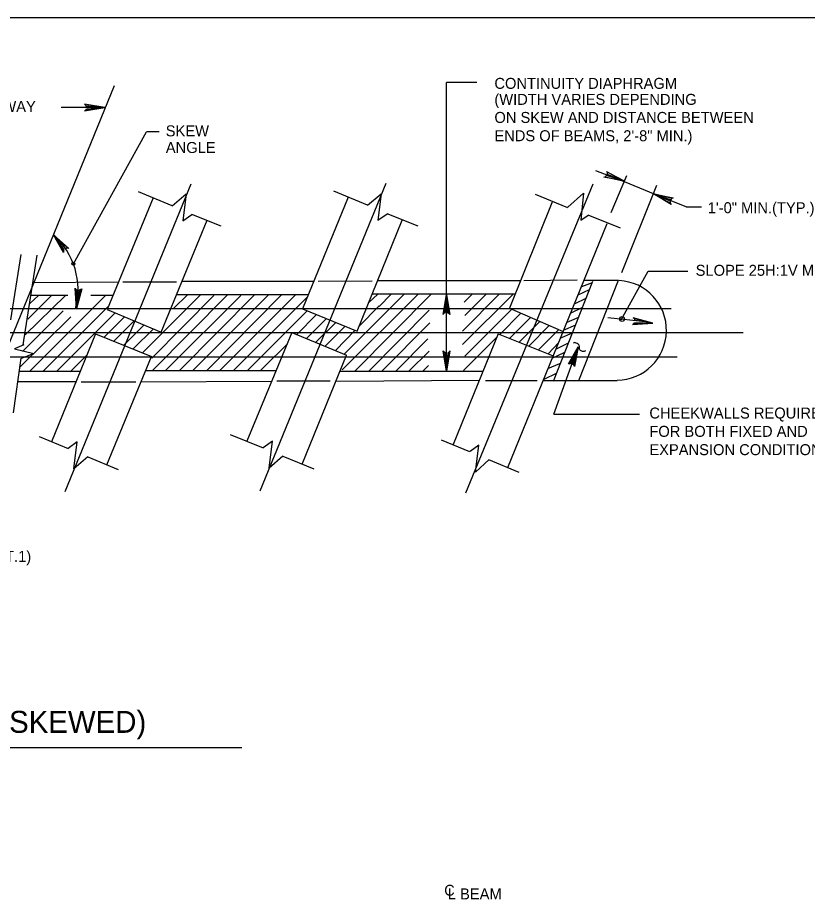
# Model space of a CAD drawing. Extents: x 639980 to 641204, y 298038 to 300414.
# Drawn here: x 640257.8 to 640473.5, y 298970 to 299210.8 of the extents above; entities that cross this region are included whole.
import ezdxf

# ---------------------------------------------------------------- set-up
doc = ezdxf.new("R2010")
doc.units = 0
doc.layers.add('2', color=7, linetype='Continuous')
doc.layers.add('3', color=7, linetype='Continuous')

msp = doc.modelspace()

# ---------------------------------------------------------------- linework, layer by layer
at = {"layer": '2'}
for p, q in [((640020.31, 299210.78), (640806.31, 299210.78)), ((640237.04, 299076.6), (640284.31, 299192.29)), ((640374.92, 299135.1), (640374.92, 299193.06)), ((640383.2, 299193.06), (640374.92, 299193.06)), ((640281.64, 299186.27), (640269.76, 299186.27)), ((640273.04, 299143.56), (640293.02, 299179.56)), ((640296.44, 299179.56), (640293.02, 299179.56)), ((640423.49, 299165.91), (640415.75, 299168.97)), ((640419.93, 299157.56), (640424.21, 299167.71)), ((640305.08, 299165.34), (640270.7, 299081.28)), ((640358.36, 299165.52), (640323.98, 299081.46)), ((640414.88, 299165.34), (640380.14, 299080.92)), ((640422.8, 299141.22), (640432.35, 299164.99)), ((640431.95, 299162.49), (640423.49, 299165.91)), ((640300.04, 299159.4), (640290.86, 299163.18)), ((640353.32, 299159.58), (640344.14, 299163.36)), ((640408.04, 299158.86), (640399.22, 299162.46)), ((640440.41, 299159.07), (640431.41, 299162.67)), ((640294.82, 299161.56), (640282.29, 299131.05)), ((640348.1, 299161.74), (640335.57, 299131.23)), ((640403.9, 299160.66), (640392.09, 299131.41)), ((640367.18, 299153.82), (640358.72, 299157.24)), ((640440.41, 299159.07), (640444.55, 299159.07)), ((640297.06, 299124.93), (640309.58, 299155.44)), ((640313.36, 299153.82), (640305.44, 299157.06)), ((640350.55, 299125.17), (640362.86, 299155.44)), ((640422.44, 299153.28), (640413.62, 299156.88)), ((640391.66, 299087.94), (640418.84, 299154.54)), ((640255.94, 299128.26), (640258.82, 299146.08)), ((640259.36, 299121.42), (640263.14, 299145.9)), ((640422.62, 299128.26), (640430, 299141.58)), ((640430, 299141.58), (640440.8, 299141.58)), ((640285.28, 299138.52), (640262.06, 299138.34)), ((640301.19, 299138.52), (640286.53, 299138.52)), ((640338.64, 299138.7), (640302.74, 299138.7)), ((640354.65, 299138.84), (640339.87, 299138.73)), ((640395.11, 299138.88), (640356.13, 299138.88)), ((640410.59, 299139.05), (640396.03, 299138.93)), ((640404.12, 299111.47), (640414.92, 299138.83)), ((640411.1, 299111.7), (640421.9, 299139.06)), ((640414.74, 299138.38), (640411.82, 299137.26)), ((640412.54, 299139.06), (640421.9, 299139.06)), ((640410.92, 299135.1), (640414.01, 299136.53)), ((640271.53, 299134.92), (640261.52, 299134.92)), ((640283.84, 299134.92), (640277.85, 299134.92)), ((640337.12, 299135.1), (640301.3, 299135.1)), ((640393.64, 299135.28), (640354.58, 299135.28)), ((640374.92, 299114.22), (640374.92, 299135.1)), ((640410.02, 299132.76), (640413.08, 299134.17)), ((640103.87, 299131.32), (640436.3, 299131.32)), ((640282.29, 299131.05), (640297.06, 299124.93)), ((640335.57, 299131.23), (640350.55, 299125.17)), ((640392.09, 299131.41), (640406.83, 299125.1)), ((640408.76, 299130.06), (640412.12, 299131.74)), ((640410.97, 299128.88), (640407.79, 299127.52)), ((640429.28, 299127.72), (640419.02, 299128.8)), ((640406.88, 299125.4), (640410.25, 299126.85)), ((640455.92, 299124.66), (640202.59, 299124.66)), ((640279.1, 299124.45), (640267.1, 299094.96)), ((640279.1, 299124.45), (640294.39, 299118.27)), ((640332.67, 299124.84), (640320.38, 299095.14)), ((640332.67, 299124.84), (640347.67, 299118.63)), ((640389.08, 299124.42), (640376.72, 299094.24)), ((640389.08, 299124.42), (640404.01, 299118.45)), ((640405.98, 299123.23), (640409.32, 299124.66)), ((640404.98, 299120.34), (640408.27, 299121.98)), ((640403.8, 299117.79), (640407.08, 299119.3)), ((640404.26, 299102.52), (640410.92, 299120.88)), ((640148.46, 299118.18), (640437.92, 299118.18)), ((640256.66, 299102.88), (640258.82, 299117.82)), ((640282.22, 299088.66), (640294.39, 299118.27)), ((640335.5, 299088.84), (640347.67, 299118.63)), ((640402.62, 299114.95), (640405.91, 299116.36)), ((640258.28, 299114.22), (640275.02, 299114.22)), ((640292.66, 299114.4), (640328.3, 299114.4)), ((640345.94, 299114.22), (640385, 299114.22)), ((640291.58, 299111.34), (640327.17, 299111.54)), ((640343.15, 299111.52), (640328.6, 299111.52)), ((640344.76, 299111.5), (640383.89, 299111.74)), ((640385.55, 299111.7), (640399.65, 299111.7)), ((640401.36, 299111.7), (640421.54, 299111.7)), ((640401.56, 299112.06), (640404.98, 299113.66)), ((640273.76, 299111.34), (640257.92, 299111.34)), ((640275.14, 299111.34), (640290.14, 299111.34)), ((640404.26, 299102.52), (640427.66, 299102.52)), ((640263.68, 299096.4), (640271.6, 299093.16)), ((640315.88, 299096.94), (640324.88, 299093.34)), ((640373.48, 299095.5), (640381.22, 299092.26)), ((640277, 299090.82), (640285.28, 299087.4)), ((640330.28, 299091), (640338.74, 299087.58)), ((640386.44, 299090.1), (640394.72, 299086.68)), ((640202.29, 299011.49), (640319.04, 299011.49))]:
    msp.add_line(p, q, dxfattribs=at)
for points in [[(640276.42, 299185.55), (640276.6, 299185.91), (640281.64, 299186.27), (640276.42, 299185.55), (640276.06, 299185.37), (640281.64, 299186.27), (640276.6, 299186.45), (640276.42, 299186.81), (640281.64, 299186.27), (640276.06, 299187.17), (640276.42, 299186.81)], [(640276.42, 299185.55), (640276.6, 299185.91), (640281.64, 299186.27), (640276.42, 299185.55), (640276.06, 299185.37), (640281.64, 299186.27), (640276.6, 299186.45), (640276.42, 299186.81), (640281.64, 299186.27), (640276.06, 299187.17), (640276.42, 299186.81)], [(640418.81, 299168.61), (640418.81, 299168.07), (640423.49, 299166.09), (640418.81, 299168.61), (640418.63, 299168.79), (640423.49, 299166.09), (640418.63, 299167.71), (640418.27, 299167.35), (640423.49, 299166.09), (640417.91, 299167.17), (640418.27, 299167.35)], [(640300.04, 299159.4), (640303.82, 299162.64), (640302.92, 299155.26), (640305.44, 299157.06)], [(640353.32, 299159.58), (640357.1, 299162.64), (640356.2, 299155.44), (640358.72, 299157.24)], [(640408.04, 299159.04), (640412.36, 299162.82), (640411.64, 299155.44), (640413.62, 299156.88)], [(640436.09, 299160.15), (640436.09, 299160.69), (640431.41, 299162.67), (640436.09, 299160.15), (640436.27, 299159.79), (640431.41, 299162.67), (640436.27, 299161.05), (640436.45, 299161.41), (640431.41, 299162.67), (640436.81, 299161.59), (640436.45, 299161.41)], [(640270.34, 299146.98), (640270.52, 299147.34), (640267.64, 299151.48), (640270.34, 299146.98), (640270.34, 299146.62), (640267.64, 299151.48), (640270.88, 299147.7), (640271.42, 299147.88), (640267.64, 299151.48), (640271.78, 299147.7), (640271.42, 299147.88)], [(640275.02, 299136.54), (640274.66, 299136.36), (640273.94, 299131.32), (640275.02, 299136.54), (640275.38, 299136.72), (640273.94, 299131.32), (640274.12, 299136.36), (640273.76, 299136.54), (640273.94, 299131.32), (640273.58, 299136.9), (640273.76, 299136.54)], [(640259.9, 299124.12), (640270.88, 299134.92)], [(640260.62, 299128.44), (640267.1, 299134.92)], [(640261.16, 299114.22), (640281.86, 299134.92)], [(640261.16, 299132.76), (640263.5, 299134.92)], [(640294.46, 299117.82), (640311.39, 299134.93)], [(640294.64, 299114.4), (640315.02, 299134.96)], [(640298.24, 299114.4), (640318.75, 299134.9)], [(640300.5, 299131.42), (640304.18, 299135.1)], [(640302.02, 299114.4), (640322.59, 299135.15)], [(640303.22, 299130.54), (640307.65, 299134.97)], [(640305.68, 299114.46), (640326.32, 299135.1)], [(640309.55, 299114.55), (640329.92, 299135.1)], [(640312.97, 299114.37), (640333.7, 299135.1)], [(640316.78, 299114.4), (640336.94, 299134.55)], [(640346.48, 299114.58), (640367.18, 299135.28)], [(640347.02, 299118.9), (640363.4, 299135.28)], [(640349.9, 299114.22), (640370.78, 299135.28)], [(640353.72, 299132.95), (640356.2, 299135.28)], [(640356.56, 299131.86), (640359.8, 299135.28)], [(640374.2, 299130.06), (640374.56, 299130.24), (640374.92, 299135.1), (640374.2, 299130.06), (640374.02, 299129.7), (640374.92, 299135.1), (640375.1, 299130.24), (640375.46, 299130.06), (640374.92, 299135.1), (640375.82, 299129.7), (640375.46, 299130.06)], [(640379.26, 299125.13), (640389.32, 299135.28)], [(640379.34, 299121.52), (640393.1, 299135.28)], [(640379.72, 299133.04), (640381.94, 299135.28)], [(640379.91, 299129.47), (640385.72, 299135.28)], [(640259.18, 299119.62), (640270.28, 299130.72)], [(640264.76, 299114.22), (640282.58, 299131.86)], [(640291.89, 299119.21), (640303.51, 299130.83)], [(640320.56, 299114.4), (640336.87, 299130.71)], [(640351.09, 299126.48), (640356.56, 299132.04)], [(640353.68, 299114.22), (640370.22, 299130.9)], [(640379.96, 299118.36), (640392.74, 299131.14)], [(640258.46, 299115.3), (640272.38, 299129.09)], [(640273.94, 299119.62), (640284.47, 299130.15)], [(640281.43, 299123.51), (640287.02, 299129.1)], [(640334.04, 299124.28), (640339.43, 299129.67)], [(640336.71, 299123.17), (640342.12, 299128.58)], [(640389.47, 299124.26), (640395.26, 299130.06)], [(640392.17, 299123.18), (640397.9, 299128.92)], [(640426.04, 299127.18), (640426.22, 299127.54), (640431.26, 299127.36), (640426.04, 299127.18), (640425.68, 299127), (640431.26, 299127.36), (640426.4, 299128.08), (640426.22, 299128.62), (640431.26, 299127.36), (640425.86, 299128.8), (640426.22, 299128.62)], [(640284.12, 299122.42), (640289.69, 299127.99)], [(640286.81, 299121.33), (640292.36, 299126.88)], [(640339.26, 299122.12), (640344.69, 299127.54)], [(640341.8, 299121.06), (640347.25, 299126.51)], [(640357.28, 299114.22), (640370.34, 299127.39)], [(640394.74, 299122.16), (640400.42, 299127.84)], [(640397.42, 299121.06), (640402.97, 299126.75)], [(640289.38, 299120.3), (640294.91, 299125.82)], [(640344.6, 299119.9), (640350.01, 299125.39)], [(640379.6, 299114.4), (640388.7, 299123.5)], [(640400.01, 299120.05), (640405.59, 299125.63)], [(640259.54, 299121.42), (640257.02, 299120.34), (640262.24, 299119.08), (640258.64, 299117.64)], [(640325.24, 299115.48), (640331.31, 299121.55)], [(640361.06, 299114.22), (640369.83, 299123.07)], [(640402.7, 299118.97), (640405.59, 299122.07)], [(640268.54, 299114.22), (640274.12, 299119.8)], [(640272.14, 299114.04), (640276.82, 299118.72)], [(640364.66, 299114.22), (640370.18, 299119.74)], [(640375.64, 299119.44), (640375.28, 299119.26), (640374.92, 299114.22), (640375.64, 299119.44), (640375.82, 299119.8), (640374.92, 299114.22), (640374.74, 299119.26), (640374.38, 299119.44), (640374.92, 299114.22), (640374.02, 299119.8), (640374.38, 299119.44)], [(640380.23, 299118.63), (640380.5, 299118.9)], [(640408.4, 299116.2), (640408.94, 299116.38), (640410.92, 299120.88), (640408.4, 299116.2), (640408.22, 299116.2), (640410.92, 299120.88), (640409.3, 299116.2), (640409.66, 299115.84), (640410.92, 299120.88), (640409.84, 299115.48), (640409.66, 299115.84)], [(640324.16, 299114.4), (640325.78, 299116.02)], [(640368.44, 299114.22), (640370.01, 299115.8)], [(640277, 299090.82), (640273.22, 299087.58), (640274.12, 299094.96), (640271.6, 299093.16)], [(640330.28, 299091), (640326.5, 299087.76), (640327.4, 299095.14), (640324.88, 299093.34)], [(640386.62, 299090.1), (640382.84, 299086.68), (640383.74, 299094.06), (640381.4, 299092.26)]]:
    msp.add_lwpolyline(points, dxfattribs=at)
for centre, radius in [((640273.04, 299143.56), 0.406), ((640422.87, 299128.48), 0.65)]:
    msp.add_circle(centre, radius, dxfattribs=at)
for centre, radius, start, end in [((640254.46, 299136.5), 19.87, 344.6208, 48.6198), ((640421.37, 299125.38), 13.62, 270.6015, 86.9793)]:
    msp.add_arc(centre, radius, start, end, dxfattribs=at)
msp.add_spline([(640412.86, 299119.79), (640412.56, 299119.64), (640411.66, 299119.79), (640411.21, 299120.39), (640411.21, 299120.99), (640410.91, 299121.59), (640410.31, 299121.89), (640410.01, 299122.04), (640409.56, 299121.89)], degree=3, dxfattribs=at)

# ---------------------------------------------------------------- texts
for s, height, p in [('  OF ROADWAY', 2.9998, (640233.15, 299185.01)), ('SKEW', 3, (640298.27, 299178.36)), ('ANGLE', 3, (640298.29, 299173.81)), ('1\'-0" MIN.(TYP.)', 2.9998, (640446.26, 299157.37)), ('SLOPE 25H:1V MIN.', 2.9996, (640442.96, 299140.28)), ('CHEEKWALLS REQUIRED', 2.9998, (640430.32, 299101.3)), ('FOR BOTH FIXED AND', 2.9998, (640430.32, 299096.3)), ('EXPANSION CONDITIONS.', 2.9998, (640430.32, 299091.3)), ('(SEE NOTE 9 ON SHT.1)', 3, (640215.62, 299062.16)), ('PIER PLAN - (SKEWED) ', 6, (640203.79, 299015.47)), ('C', 2.97, (640374.31, 298971)), ('L BEAM', 3, (640375.29, 298969.99))]:
    msp.add_text(s, height=height, dxfattribs=at).set_placement(p)
at = {"layer": '3'}
for s, p in [('CONTINUITY DIAPHRAGM', (640388.01, 299191.33)), ('(WIDTH VARIES DEPENDING', (640388.01, 299186.96)), ('ON SKEW AND DISTANCE BETWEEN', (640388.01, 299182.03)), ('ENDS OF BEAMS, 2\'-8" MIN.)', (640388.01, 299177.03))]:
    msp.add_text(s, height=2.9969, dxfattribs=at).set_placement(p)

doc.saveas('drawing.dxf')
